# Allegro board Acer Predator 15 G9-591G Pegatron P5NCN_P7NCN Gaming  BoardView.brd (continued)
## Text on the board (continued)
IN2: list("[Spacing] IN2" "98.Line to Route Keepout" "0 MIL [DEFAULT]" "0 MIL" "0.00 MIL" "DRC ERROR CLASS/IN2" "[Shape] Route Keepout/In2 ((-630.0 2141.43) (-45.0 2716.89))" "[Line] N129963384 ((-343.9 2671.1) (-269.5 2745.5))" list(-318.110000 2696.890000) nil)@@@list("kelly1_pan" "2015/09/04 14:25:34" nil "P143000035-PC" "n3-p5-p7ncn.20")@@@list("jennifer_hsu" "2015/09/07 11:45:41" nil "P143000039-PC" "n3-p5-p7ncn.20") | list("[Spacing] IN2" "94.Shape to Route Keepin" "0 MIL [DEFAULT]" "0 MIL" "0.00 MIL" "DRC ERROR CLASS/IN2" "[Shape] Route Keepin/All ((-917.01 -373.7) (9771.34 6936.7))" "[In2 Shape] GND ((-137.47 -373.69) (9771.34 1245.0))" list(137.480000 381.890000) nil)@@@list("kelly1_pan" "2015/09/04 14:25:31" nil "P143000035-PC" "n3-p5-p7ncn.20")@@@list("jennifer_hsu" "2015/09/07 11:45:37" nil "P143000039-PC" "n3-p5-p7ncn.20") | list("[Spacing] IN2" "91.Shape to Route Keepin" "0 MIL [DEFAULT]" "0 MIL" "0.00 MIL" "DRC ERROR CLASS/IN2" "[Shape] Route Keepin/All ((-917.01 -373.7) (9771.34 6936.7))" "[In2 Shape] GND_LED ((5460.94 5736.53) (7231.96 6031.18))" list(6260.100000 5736.540000) nil)@@@list("kelly1_pan" "2015/09/04 14:25:28" nil "P143000035-PC" "n3-p5-p7ncn.20")@@@list("jennifer_hsu" "2015/09/07 11:45:35" nil "P143000039-PC" "n3-p5-p7ncn.20") | list("[Spacing] IN2" "92.Shape to Route Keepin" "0 MIL [DEFAULT]" "0 MIL" "0.00 MIL" "DRC ERROR CLASS/IN2" "[Shape] Route Keepin/All ((-917.01 -373.7) (9771.34 6936.7))" "[In2 Shape] LAN_GND ((9292.77 4680.51) (9698.51 5486.88))" list(9332.360000 5367.300000) nil)@@@list("kelly1_pan" "2015/09/04 14:25:29" nil "P143000035-PC" "n3-p5-p7ncn.20")@@@list("jennifer_hsu" "2015/09/07 11:45:36" nil "P143000039-PC" "n3-p5-p7ncn.20") | list("[Spacing] IN2" "93.Shape to Route Keepin" "0 MIL [DEFAULT]" "0 MIL" "0.00 MIL" "DRC ERROR CLASS/IN2" "[Shape] Route Keepin/All ((-917.01 -373.7) (9771.34 6936.7))" "[In2 Shape] GND ((9262.9 1450.04) (9668.98 2194.61))" list(9367.790000 1612.100000) nil)@@@list("kelly1_pan" "2015/09/04 14:25:30" nil "P143000035-PC" "n3-p5-p7ncn.20")@@@list("jennifer_hsu" "2015/09/07 11:45:37" nil "P143000039-PC" "n3-p5-p7ncn.20") | list("[Spacing] IN2" "96.Shape to Route Keepin" "0 MIL [DEFAULT]" "0 MIL" "0.00 MIL" "DRC ERROR CLASS/IN2" "[Shape] Route Keepin/All ((-917.01 -373.7) (9771.34 6936.7))" "[In2 Shape] GND ((-917.0 1310.0) (9698.51 6936.7))" list(9434.090000 2759.760000) nil)@@@list("kelly1_pan" "2015/09/04 14:25:33" nil "P143000035-PC" "n3-p5-p7ncn.20")@@@list("jennifer_hsu" "2015/09/07 11:45:39" nil "P143000039-PC" "n3-p5-p7ncn.20") | list("[Spacing] IN2" "97.Shape to Route Keepout" "0 MIL [DEFAULT]" "0 MIL" "0.00 MIL" "DRC ERROR CLASS/IN2" "[Shape] Route Keepout/All ((9638.0 5487.0) (9744.0 5507.0))" "[In2 Shape] GND ((-917.0 1310.0) (9698.51 6936.7))" list(9638.000000 5507.000000) nil)@@@list("kelly1_pan" "2015/09/04 14:25:33" nil "P143000035-PC" "n3-p5-p7ncn.20")@@@list("jennifer_hsu" "2015/09/07 11:45:39" nil "P143000039-PC" "n3-p5-p7ncn.20") | list("[Spacing] IN2" "95.Shape to Route Keepout" "0 MIL [DEFAULT]" "0 MIL" "0.00 MIL" "DRC ERROR CLASS/IN2" "[Shape] Route Keepout/All ((-937.01 -393.7) (9791.34 6956.69))" "[In2 Shape] GND ((-917.0 1310.0) (9698.51 6936.7))" list(9676.990000 2758.020000) nil)@@@list("kelly1_pan" "2015/09/04 14:25:32" nil "P143000035-PC" "n3-p5-p7ncn.20")@@@list("jennifer_hsu" "2015/09/07 11:45:38" nil "P143000039-PC" "n3-p5-p7ncn.20")
IN3: list("[Spacing] IN3" "104.Shape to Route Keepin" "0 MIL [DEFAULT]" "0 MIL" "0.00 MIL" "DRC ERROR CLASS/IN3" "[Shape] Route Keepin/All ((-917.01 -373.7) (9771.34 6936.7))" "[In3 Shape] GND ((-137.47 -373.69) (9771.34 1235.0))" list(137.480000 381.890000) nil)@@@list("kelly1_pan" "2015/09/04 14:25:39" nil "P143000035-PC" "n3-p5-p7ncn.20")@@@list("jennifer_hsu" "2015/09/07 11:45:45" nil "P143000039-PC" "n3-p5-p7ncn.20") | list("[Spacing] IN3" "99.Shape to Route Keepin" "0 MIL [DEFAULT]" "0 MIL" "0.00 MIL" "DRC ERROR CLASS/IN3" "[Shape] Route Keepin/All ((-917.01 -373.7) (9771.34 6936.7))" "[In3 Shape] GND_LED ((5460.94 5736.53) (7231.96 6031.18))" list(6260.100000 5736.540000) nil)@@@list("kelly1_pan" "2015/09/04 14:25:35" nil "P143000035-PC" "n3-p5-p7ncn.20")@@@list("jennifer_hsu" "2015/09/07 11:45:41" nil "P143000039-PC" "n3-p5-p7ncn.20") | list("[Spacing] IN3" "105.Shape to Route Keepin" "0 MIL [DEFAULT]" "0 MIL" "0.00 MIL" "DRC ERROR CLASS/IN3" "[Shape] Route Keepin/All ((-917.01 -373.7) (9771.34 6936.7))" "[In3 Shape] GND ((-917.0 1322.0) (9698.51 6936.7))" list(6742.230000 2896.930000) nil)@@@list("kelly1_pan" "2015/09/04 14:25:40" nil "P143000035-PC" "n3-p5-p7ncn.20")@@@list("jennifer_hsu" "2015/09/07 11:45:46" nil "P143000039-PC" "n3-p5-p7ncn.20") | list("[Spacing] IN3" "100.Shape to Route Keepin" "0 MIL [DEFAULT]" "0 MIL" "0.00 MIL" "DRC ERROR CLASS/IN3" "[Shape] Route Keepin/All ((-917.01 -373.7) (9771.34 6936.7))" "[In3 Shape] LAN_GND ((9292.77 4680.51) (9698.51 5486.88))" list(9332.360000 5367.300000) nil)@@@list("kelly1_pan" "2015/09/04 14:25:36" nil "P143000035-PC" "n3-p5-p7ncn.20")@@@list("jennifer_hsu" "2015/09/07 11:45:42" nil "P143000039-PC" "n3-p5-p7ncn.20") | list("[Spacing] IN3" "101.Shape to Route Keepin" "0 MIL [DEFAULT]" "0 MIL" "0.00 MIL" "DRC ERROR CLASS/IN3" "[Shape] Route Keepin/All ((-917.01 -373.7) (9771.34 6936.7))" "[In3 Shape] GND ((9256.0 1450.04) (9668.98 2194.61))" list(9367.790000 1612.100000) nil)@@@list("kelly1_pan" "2015/09/04 14:25:37" nil "P143000035-PC" "n3-p5-p7ncn.20")@@@list("jennifer_hsu" "2015/09/07 11:45:43" nil "P143000039-PC" "n3-p5-p7ncn.20") | list("[Spacing] IN3" "103.Shape to Route Keepin" "0 MIL [DEFAULT]" "0 MIL" "0.00 MIL" "DRC ERROR CLASS/IN3" "[Shape] Route Keepin/All ((-917.01 -373.7) (9771.34 6936.7))" "[In3 Shape] GND ((9258.0 2335.0) (9698.5 3131.19))" list(9368.890000 2739.600000) nil)@@@list("kelly1_pan" "2015/09/04 14:25:38" nil "P143000035-PC" "n3-p5-p7ncn.20")@@@list("jennifer_hsu" "2015/09/07 11:45:44" nil "P143000039-PC" "n3-p5-p7ncn.20") | list("[Spacing] IN3" "108.Shape to Route Keepout" "0 MIL [DEFAULT]" "0 MIL" "0.00 MIL" "DRC ERROR CLASS/IN3" "[Shape] Route Keepout/All ((9638.0 5487.0) (9744.0 5507.0))" "[In3 Shape] GND ((-917.0 1322.0) (9698.51 6936.7))" list(9638.000000 5507.000000) nil)@@@list("kelly1_pan" "2015/09/04 14:25:42" nil "P143000035-PC" "n3-p5-p7ncn.20")@@@list("jennifer_hsu" "2015/09/07 11:45:47" nil "P143000039-PC" "n3-p5-p7ncn.20") | list("[Spacing] IN3" "102.Shape to Route Keepout" "0 MIL [DEFAULT]" "0 MIL" "0.00 MIL" "DRC ERROR CLASS/IN3" "[Shape] Route Keepout/All ((-937.01 -393.7) (9791.34 6956.69))" "[In3 Shape] GND ((9258.0 2335.0) (9698.5 3131.19))" list(9676.990000 2758.020000) nil)@@@list("kelly1_pan" "2015/09/04 14:25:38" nil "P143000035-PC" "n3-p5-p7ncn.20")@@@list("jennifer_hsu" "2015/09/07 11:45:44" nil "P143000039-PC" "n3-p5-p7ncn.20") | list("[Spacing] IN3" "107.Shape to Route Keepout" "0 MIL [DEFAULT]" "0 MIL" "0.00 MIL" "DRC ERROR CLASS/IN3" "[Shape] Route Keepout/All ((9655.0 4660.5) (9762.0 4680.5))" "[In3 Shape] GND ((-917.0 1322.0) (9698.51 6936.7))" list(9678.600000 4660.500000) nil)@@@list("kelly1_pan" "2015/09/04 14:25:42" nil "P143000035-PC" "n3-p5-p7ncn.20")@@@list("jennifer_hsu" "2015/09/07 11:45:47" nil "P143000039-PC" "n3-p5-p7ncn.20") | list("[Spacing] IN3" "106.Shape to Route Keepout" "0 MIL [DEFAULT]" "0 MIL" "0.00 MIL" "DRC ERROR CLASS/IN3" "[Shape] Route Keepout/All ((8775.0 4660.0) (9725.0 5506.4))" "[In3 Shape] GND ((-917.0 1322.0) (9698.51 6936.7))" list(9678.600000 4660.000000) nil)@@@list("kelly1_pan" "2015/09/04 14:25:41" nil "P143000035-PC" "n3-p5-p7ncn.20")@@@list("jennifer_hsu" "2015/09/07 11:45:46" nil "P143000039-PC" "n3-p5-p7ncn.20")
GND3: list("[Spacing] GND3" "132.Shape to Route Keepout" "0 MIL [DEFAULT]" "0 MIL" "0.00 MIL" "DRC ERROR CLASS/GND3" "[Shape] Route Keepout/All ((-831.77 4457.88) (-768.15 4521.5))" "[Gnd3 Shape] +AC_BAT_SYS ((-885.0 1165.0) (230.0 6905.0))" list(-830.000000 4500.150000) nil)@@@list("kelly1_pan" "2015/09/04 14:26:00" nil "P143000035-PC" "n3-p5-p7ncn.20")@@@list("jennifer_hsu" "2015/09/07 11:46:08" nil "P143000039-PC" "n3-p5-p7ncn.20") | list("[Spacing] GND3" "128.Shape to Route Keepout" "0 MIL [DEFAULT]" "0 MIL" "0.00 MIL" "DRC ERROR CLASS/GND3" "[Shape] Route Keepout/All ((-831.77 5250.24) (-768.15 5313.86))" "[Gnd3 Shape] GND ((-917.01 -373.7) (9771.34 6936.7))" list(-829.340000 5294.250000) nil)@@@list("kelly1_pan" "2015/09/04 14:25:57" nil "P143000035-PC" "n3-p5-p7ncn.20")@@@list("jennifer_hsu" "2015/09/07 11:46:04" nil "P143000039-PC" "n3-p5-p7ncn.20") | list("[Spacing] GND3" "126.Shape to Route Keepout" "0 MIL [DEFAULT]" "0 MIL" "0.00 MIL" "DRC ERROR CLASS/GND3" "[Shape] Route Keepout/All ((-831.77 4457.88) (-768.15 4521.5))" "[Gnd3 Shape] GND ((-917.01 -373.7) (9771.34 6936.7))" list(-814.260000 4518.110000) nil)@@@list("kelly1_pan" "2015/09/04 14:25:56" nil "P143000035-PC" "n3-p5-p7ncn.20")@@@list("jennifer_hsu" "2015/09/07 11:46:02" nil "P143000039-PC" "n3-p5-p7ncn.20") | list("[Spacing] GND3" "140.Thru Pin to Shape" "5 MIL [DEFAULT]" "4.99 MIL" "0.01 MIL" "DRC ERROR CLASS/GND3" "[ThruPin] GND (<uTiL>cId65<uTiL>.50) (-256.51 2263.3)" "[Gnd3 Shape] AGND ((-610.0 2155.0) (-65.0 2696.89))" list(-265.000000 2254.810000) nil)@@@list("kelly1_pan" "2015/09/04 14:26:07" nil "P143000035-PC" "n3-p5-p7ncn.20")@@@list("jennifer_hsu" "2015/09/07 11:46:16" nil "P143000039-PC" "n3-p5-p7ncn.20") | list("[Spacing] GND3" "112.Thru Pin to Shape Same Net" "5 MIL [DEFAULT]" "0 MIL" "5.00 MIL" "DRC ERROR CLASS/GND3" "[ThruPin] GND (<uTiL>cId65<uTiL>.50) (-256.51 2263.3)" "[Gnd3 Shape] GND ((-917.01 -373.7) (9771.34 6936.7))" list(-255.000000 2275.200000) nil)@@@list("kelly1_pan" "2015/09/04 14:25:45" nil "P143000035-PC" "n3-p5-p7ncn.20")@@@list("jennifer_hsu" "2015/09/07 11:45:50" nil "P143000039-PC" "n3-p5-p7ncn.20") | list("[Spacing] GND3" "113.Thru Pin to Shape Same Net" "5 MIL [DEFAULT]" "0 MIL" "5.00 MIL" "DRC ERROR CLASS/GND3" "[ThruPin] GND (<uTiL>cId65<uTiL>.51) (-256.51 2422.28)" "[Gnd3 Shape] GND ((-917.01 -373.7) (9771.34 6936.7))" list(-249.320000 2431.890000) nil)@@@list("kelly1_pan" "2015/09/04 14:25:46" nil "P143000035-PC" "n3-p5-p7ncn.20")@@@list("jennifer_hsu" "2015/09/07 11:45:51" nil "P143000039-PC" "n3-p5-p7ncn.20") | list("[Spacing] GND3" "121.Shape to Route Keepout" "0 MIL [DEFAULT]" "0 MIL" "0.00 MIL" "DRC ERROR CLASS/GND3" "[Shape] Route Keepout/All ((-133.59 333.73) (-56.95 410.36))" "[Gnd3 Shape] GND ((-917.01 -373.7) (9771.34 6936.7))" list(-95.270000 410.360000) nil)@@@list("kelly1_pan" "2015/09/04 14:25:52" nil "P143000035-PC" "n3-p5-p7ncn.20")@@@list("jennifer_hsu" "2015/09/07 11:45:57" nil "P143000039-PC" "n3-p5-p7ncn.20") | list("[Spacing] GND3" "120.Shape to Route Keepout" "0 MIL [DEFAULT]" "0 MIL" "0.00 MIL" "DRC ERROR CLASS/GND3" "[Shape] Route Keepout/All ((-123.21 218.12) (-12.21 329.12))" "[Gnd3 Shape] GND ((-917.01 -373.7) (9771.34 6936.7))" list(-67.710000 329.120000) nil)@@@list("kelly1_pan" "2015/09/04 14:25:51" nil "P143000035-PC" "n3-p5-p7ncn.20")@@@list("jennifer_hsu" "2015/09/07 11:45:57" nil "P143000039-PC" "n3-p5-p7ncn.20") | list("[Spacing] GND3" "134.Shape to Thru Via" "5 MIL [DEFAULT]" "0 MIL" "5.00 MIL" "DRC ERROR CLASS/GND3" "[ThruVia] GND (VIA30D18A40) (249.0 5774.89)" "[Gnd3 Shape] +VCCGT ((-515.0 4910.0) (735.0 5765.0))" list(260.280000 5765.000000) nil)@@@list("kelly1_pan" "2015/09/04 14:26:02" nil "P143000035-PC" "n3-p5-p7ncn.20")@@@list("jennifer_hsu" "2015/09/07 11:46:11" nil "P143000039-PC" "n3-p5-p7ncn.20") | list("[Spacing] GND3" "117.Shape to Thru Via Same Net" "5 MIL [DEFAULT]" "0 MIL" "5.00 MIL" "DRC ERROR CLASS/GND3" "[ThruVia] GND (VIA30D18A40) (249.0 5774.89)" "[Gnd3 Shape] GND ((-917.01 -373.7) (9771.34 6936.7))" list(264.000000 5775.000000) nil)@@@list("kelly1_pan" "2015/09/04 14:25:49" nil "P143000035-PC" "n3-p5-p7ncn.20")@@@list("jennifer_hsu" "2015/09/07 11:45:54" nil "P143000039-PC" "n3-p5-p7ncn.20") | list("[Spacing] GND3" "136.Shape to Thru Via" "5 MIL [DEFAULT]" "0 MIL" "5.00 MIL" "DRC ERROR CLASS/GND3" "[ThruVia] GND (VIA30D18A40) (284.0 5774.89)" "[Gnd3 Shape] +VCCGT ((-515.0 4910.0) (735.0 5765.0))" list(295.280000 5765.000000) nil)@@@list("kelly1_pan" "2015/09/04 14:26:04" nil "P143000035-PC" "n3-p5-p7ncn.20")@@@list("jennifer_hsu" "2015/09/07 11:46:13" nil "P143000039-PC" "n3-p5-p7ncn.20") | list("[Spacing] GND3" "119.Shape to Thru Via Same Net" "5 MIL [DEFAULT]" "0 MIL" "5.00 MIL" "DRC ERROR CLASS/GND3" "[ThruVia] GND (VIA30D18A40) (284.0 5774.89)" "[Gnd3 Shape] GND ((-917.01 -373.7) (9771.34 6936.7))" list(299.000000 5775.000000) nil)@@@list("kelly1_pan" "2015/09/04 14:25:51" nil "P143000035-PC" "n3-p5-p7ncn.20")@@@list("jennifer_hsu" "2015/09/07 11:45:56" nil "P143000039-PC" "n3-p5-p7ncn.20") | list("[Spacing] GND3" "135.Shape to Thru Via" "5 MIL [DEFAULT]" "0 MIL" "5.00 MIL" "DRC ERROR CLASS/GND3" "[ThruVia] GND (VIA30D18A40) (319.0 5774.89)" "[Gnd3 Shape] +VCCGT ((-515.0 4910.0) (735.0 5765.0))" list(330.280000 5765.000000) nil)@@@list("kelly1_pan" "2015/09/04 14:26:03" nil "P143000035-PC" "n3-p5-p7ncn.20")@@@list("jennifer_hsu" "2015/09/07 11:46:12" nil "P143000039-PC" "n3-p5-p7ncn.20") | list("[Spacing] GND3" "118.Shape to Thru Via Same Net" "5 MIL [DEFAULT]" "0 MIL" "5.00 MIL" "DRC ERROR CLASS/GND3" "[ThruVia] GND (VIA30D18A40) (319.0 5774.89)" "[Gnd3 Shape] GND ((-917.01 -373.7) (9771.34 6936.7))" list(334.000000 5775.000000) nil)@@@list("kelly1_pan" "2015/09/04 14:25:50" nil "P143000035-PC" "n3-p5-p7ncn.20")@@@list("jennifer_hsu" "2015/09/07 11:45:55" nil "P143000039-PC" "n3-p5-p7ncn.20") | list("[Spacing] GND3" "133.Shape to Thru Via" "5 MIL [DEFAULT]" "0 MIL" "5.00 MIL" "DRC ERROR CLASS/GND3" "[ThruVia] GND (VIA18D8A28) (743.5 5438.5)" "[Gnd3 Shape] +VCCGT ((-515.0 4910.0) (735.0 5765.0))" list(735.000000 5441.460000) nil)@@@list("kelly1_pan" "2015/09/04 14:26:01" nil "P143000035-PC" "n3-p5-p7ncn.20")@@@list("jennifer_hsu" "2015/09/07 11:46:10" nil "P143000039-PC" "n3-p5-p7ncn.20") | list("[Spacing] GND3" "141.Shape to Thru Via" "5 MIL [DEFAULT]" "0 MIL" "5.00 MIL" "DRC ERROR CLASS/GND3" "[ThruVia] GND (VIA18D8A28) (743.5 5438.5)" "[Gnd3 Shape] +VCORE ((525.0 4910.0) (1445.0 6010.0))" list(745.000000 5447.370000) nil)@@@list("kelly1_pan" "2015/09/04 14:26:07" nil "P143000035-PC" "n3-p5-p7ncn.20")@@@list("jennifer_hsu" "2015/09/07 11:46:17" nil "P143000039-PC" "n3-p5-p7ncn.20") | list("[Spacing] GND3" "122.Shape to Route Keepout" "0 MIL [DEFAULT]" "0 MIL" "0.00 MIL" "DRC ERROR CLASS/GND3" "[Shape] Route Keepout/All ((1102.35 1665.34) (1165.35 1728.34))" "[Gnd3 Shape] GND ((-917.01 -373.7) (9771.34 6936.7))" list(1133.850000 1665.340000) nil)@@@list("kelly1_pan" "2015/09/04 14:25:53" nil "P143000035-PC" "n3-p5-p7ncn.20")@@@list("jennifer_hsu" "2015/09/07 11:45:59" nil "P143000039-PC" "n3-p5-p7ncn.20") | list("[Spacing] GND3" "123.Shape to Route Keepout" "0 MIL [DEFAULT]" "0 MIL" "0.00 MIL" "DRC ERROR CLASS/GND3" "[Shape] Route Keepout/All ((1508.04 1665.52) (1570.72 1728.2))" "[Gnd3 Shape] GND ((-917.01 -373.7) (9771.34 6936.7))" list(1539.380000 1665.520000) nil)@@@list("kelly1_pan" "2015/09/04 14:25:54" nil "P143000035-PC" "n3-p5-p7ncn.20")@@@list("jennifer_hsu" "2015/09/07 11:45:59" nil "P143000039-PC" "n3-p5-p7ncn.20") | list("[Spacing] GND3" "129.Shape to Route Keepout" "0 MIL [DEFAULT]" "0 MIL" "0.00 MIL" "DRC ERROR CLASS/GND3" "[Shape] Route Keepout/All ((1831.32 6634.59) (1885.01 6688.27))" "[Gnd3 Shape] GND ((-917.01 -373.7) (9771.34 6936.7))" list(1885.010000 6661.430000) nil)@@@list("kelly1_pan" "2015/09/04 14:25:58" nil "P143000035-PC" "n3-p5-p7ncn.20")@@@list("jennifer_hsu" "2015/09/07 11:46:05" nil "P143000039-PC" "n3-p5-p7ncn.20") | list("[Spacing] GND3" "115.Shape to Thru Via" "5 MIL [DEFAULT]" "0 MIL" "5.00 MIL" "DRC ERROR CLASS/GND3" "[ThruVia] GPIO2_GPU_EVENT# (VIA20D10A30) (2968.0 4040.0)" "[Gnd3 Shape] GND ((-917.01 -373.7) (9771.34 6936.7))" list(2959.340000 4045.000000) nil)@@@list("kelly1_pan" "2015/09/04 14:25:48" nil "P143000035-PC" "n3-p5-p7ncn.20")@@@list("jennifer_hsu" "2015/09/07 11:45:53" nil "P143000039-PC" "n3-p5-p7ncn.20") | list("[Spacing] GND3" "138.Shape to Thru Via" "5 MIL [DEFAULT]" "0 MIL" "5.00 MIL" "DRC ERROR CLASS/GND3" "[ThruVia] GPIO2_GPU_EVENT# (VIA20D10A30) (2968.0 4040.0)" "[Gnd3 Shape] +NVVDD ((2475.0 3190.0) (4740.0 5915.0))" list(2975.700000 4046.380000) nil)@@@list("kelly1_pan" "2015/09/04 14:26:05" nil "P143000035-PC" "n3-p5-p7ncn.20")@@@list("jennifer_hsu" "2015/09/07 11:46:14" nil "P143000039-PC" "n3-p5-p7ncn.20") | list("[Spacing] GND3" "130.Shape to Route Keepout" "0 MIL [DEFAULT]" "0 MIL" "0.00 MIL" "DRC ERROR CLASS/GND3" "[Shape] Route Keepout/All ((3022.0 6798.93) (3081.62 6858.55))" "[Gnd3 Shape] GND ((-917.01 -373.7) (9771.34 6936.7))" list(3051.810000 6858.550000) nil)@@@list("kelly1_pan" "2015/09/04 14:25:59" nil "P143000035-PC" "n3-p5-p7ncn.20")@@@list("jennifer_hsu" "2015/09/07 11:46:05" nil "P143000039-PC" "n3-p5-p7ncn.20") | list("[Spacing] GND3" "139.Shape to Thru Via Same Net" "5 MIL [DEFAULT]" "0 MIL" "5.00 MIL" "DRC ERROR CLASS/GND3" "[ThruVia] +NVVDD (VIA18D8A28) (3289.9 4776.8)" "[Gnd3 Shape] +NVVDD ((2475.0 3190.0) (4740.0 5915.0))" list(3293.120000 4785.200000) nil)@@@list("kelly1_pan" "2015/09/04 14:26:06" nil "P143000035-PC" "n3-p5-p7ncn.20")@@@list("jennifer_hsu" "2015/09/07 11:46:15" nil "P143000039-PC" "n3-p5-p7ncn.20") | list("[Spacing] GND3" "116.Shape to Thru Via" "5 MIL [DEFAULT]" "0 MIL" "5.00 MIL" "DRC ERROR CLASS/GND3" "[ThruVia] +NVVDD (VIA18D8A28) (3289.9 4776.8)" "[Gnd3 Shape] GND ((-917.01 -373.7) (9771.34 6936.7))" list(3298.900000 4776.830000) nil)@@@list("kelly1_pan" "2015/09/04 14:25:48" nil "P143000035-PC" "n3-p5-p7ncn.20")@@@list("jennifer_hsu" "2015/09/07 11:45:53" nil "P143000039-PC" "n3-p5-p7ncn.20") | list("[Spacing] GND3" "137.Shape to Thru Via" "5 MIL [DEFAULT]" "0 MIL" "5.00 MIL" "DRC ERROR CLASS/GND3" "[ThruVia] GND (VIA20D10A30) (3384.5 3629.6)" "[Gnd3 Shape] +NVVDD ((2475.0 3190.0) (4740.0 5915.0))" list(3390.960000 3621.960000) nil)@@@list("kelly1_pan" "2015/09/04 14:26:04" nil "P143000035-PC" "n3-p5-p7ncn.20")@@@list("jennifer_hsu" "2015/09/07 11:46:13" nil "P143000039-PC" "n3-p5-p7ncn.20") | list("[Spacing] GND3" "114.Shape to Thru Via Same Net" "5 MIL [DEFAULT]" "0 MIL" "5.00 MIL" "DRC ERROR CLASS/GND3" "[ThruVia] GND (VIA20D10A30) (3384.5 3629.6)" "[Gnd3 Shape] GND ((-917.01 -373.7) (9771.34 6936.7))" list(3393.800000 3633.270000) nil)@@@list("kelly1_pan" "2015/09/04 14:25:47" nil "P143000035-PC" "n3-p5-p7ncn.20")@@@list("jennifer_hsu" "2015/09/07 11:45:52" nil "P143000039-PC" "n3-p5-p7ncn.20") | list("[Spacing] GND3" "109.Shape to Route Keepout" "0 MIL [DEFAULT]" "0 MIL" "0.00 MIL" "DRC ERROR CLASS/GND3" "[Shape] Route Keepout/All ((6858.43 5535.43) (6984.05 5622.05))" "[Gnd3 Shape] GND_D-MIC R ((6566.9 5303.47) (7357.95 5617.8))" list(6883.030000 5617.800000) nil)@@@list("kelly1_pan" "2015/09/04 14:25:43" nil "P143000035-PC" "n3-p5-p7ncn.20")@@@list("jennifer_hsu" "2015/09/07 11:45:48" nil "P143000039-PC" "n3-p5-p7ncn.20") | list("[Spacing] GND3" "125.Shape to Route Keepout" "0 MIL [DEFAULT]" "0 MIL" "0.00 MIL" "DRC ERROR CLASS/GND3" "[Shape] Route Keepout/All ((8281.64 3112.35) (8348.26 3178.97))" "[Gnd3 Shape] GND ((-917.01 -373.7) (9771.34 6936.7))" list(8348.260000 3145.660000) nil)@@@list("kelly1_pan" "2015/09/04 14:25:55" nil "P143000035-PC" "n3-p5-p7ncn.20")@@@list("jennifer_hsu" "2015/09/07 11:46:01" nil "P143000039-PC" "n3-p5-p7ncn.20") | list("[Spacing] GND3" "124.Shape to Route Keepout" "0 MIL [DEFAULT]" "0 MIL" "0.00 MIL" "DRC ERROR CLASS/GND3" "[Shape] Route Keepout/All ((8396.75 1692.04) (8469.37 1764.66))" "[Gnd3 Shape] GND ((-917.01 -373.7) (9771.34 6936.7))" list(8469.370000 1728.350000) nil)@@@list("kelly1_pan" "2015/09/04 14:25:55" nil "P143000035-PC" "n3-p5-p7ncn.20")@@@list("jennifer_hsu" "2015/09/07 11:46:00" nil "P143000039-PC" "n3-p5-p7ncn.20") | list("[Spacing] GND3" "127.Shape to Route Keepout" "0 MIL [DEFAULT]" "0 MIL" "0.00 MIL" "DRC ERROR CLASS/GND3" "[Shape] Route Keepout/All ((8775.0 4660.0) (9725.0 5506.4))" "[Gnd3 Shape] GND ((-917.01 -373.7) (9771.34 6936.7))" list(9252.800000 4689.950000) nil)@@@list("kelly1_pan" "2015/09/04 14:25:57" nil "P143000035-PC" "n3-p5-p7ncn.20")@@@list("jennifer_hsu" "2015/09/07 11:46:03" nil "P143000039-PC" "n3-p5-p7ncn.20") | list("[Spacing] GND3" "110.Shape to Route Keepout" "0 MIL [DEFAULT]" "0 MIL" "0.00 MIL" "DRC ERROR CLASS/GND3" "[Shape] Route Keepout/All ((8775.0 4660.0) (9725.0 5506.4))" "[Gnd3 Shape] LAN_GND ((8795.0 4680.0) (9698.5 5487.0))" list(9289.360000 4680.000000) nil)@@@list("kelly1_pan" "2015/09/04 14:25:44" nil "P143000035-PC" "n3-p5-p7ncn.20")@@@list("jennifer_hsu" "2015/09/07 11:45:49" nil "P143000039-PC" "n3-p5-p7ncn.20") | list("[Spacing] GND3" "111.Shape to Route Keepin" "0 MIL [DEFAULT]" "0 MIL" "0.00 MIL" "DRC ERROR CLASS/GND3" "[Shape] Route Keepin/All ((-917.01 -373.7) (9771.34 6936.7))" "[Gnd3 Shape] LAN_GND ((8795.0 4680.0) (9698.5 5487.0))" list(9386.640000 5421.580000) nil)@@@list("kelly1_pan" "2015/09/04 14:25:44" nil "P143000035-PC" "n3-p5-p7ncn.20")@@@list("jennifer_hsu" "2015/09/07 11:45:49" nil "P143000039-PC" "n3-p5-p7ncn.20") | list("[Spacing] GND3" "131.Shape to Route Keepin" "0 MIL [DEFAULT]" "0 MIL" "0.00 MIL" "DRC ERROR CLASS/GND3" "[Shape] Route Keepin/All ((-917.01 -373.7) (9771.34 6936.7))" "[Gnd3 Shape] GND ((-917.01 -373.7) (9771.34 6936.7))" list(9433.500000 4571.180000) nil)@@@list("kelly1_pan" "2015/09/04 14:26:00" nil "P143000035-PC" "n3-p5-p7ncn.20")@@@list("jennifer_hsu" "2015/09/07 11:46:06" nil "P143000039-PC" "n3-p5-p7ncn.20")
IN4: list("[Spacing] IN4" "150.Line to Route Keepout" "0 MIL [DEFAULT]" "0 MIL" "0.00 MIL" "DRC ERROR CLASS/IN4" "[Shape] Route Keepout/In4 ((-630.0 2135.0) (-45.0 2716.89))" "[Line] AGND ((-165.0 2380.0) (-145.0 2506.89))" list(-155.000000 2451.890000) nil)@@@list("kelly1_pan" "2015/09/04 14:26:14" nil "P143000035-PC" "n3-p5-p7ncn.20")@@@list("jennifer_hsu" "2015/09/07 11:46:24" nil "P143000039-PC" "n3-p5-p7ncn.20") | list("[Spacing] IN4" "148.Shape to Route Keepin" "0 MIL [DEFAULT]" "0 MIL" "0.00 MIL" "DRC ERROR CLASS/IN4" "[Shape] Route Keepin/All ((-917.01 -373.7) (9771.34 6936.7))" "[In4 Shape] GND ((-917.0 -373.69) (9771.34 6936.7))" list(143.040000 430.660000) nil)@@@list("kelly1_pan" "2015/09/04 14:26:12" nil "P143000035-PC" "n3-p5-p7ncn.20")@@@list("jennifer_hsu" "2015/09/07 11:46:23" nil "P143000039-PC" "n3-p5-p7ncn.20") | list("[Spacing] IN4" "142.Shape to Route Keepin" "0 MIL [DEFAULT]" "0 MIL" "0.00 MIL" "DRC ERROR CLASS/IN4" "[Shape] Route Keepin/All ((-917.01 -373.7) (9771.34 6936.7))" "[In4 Shape] GND_LED ((5460.94 5736.53) (7231.96 6031.18))" list(6260.100000 5736.540000) nil)@@@list("kelly1_pan" "2015/09/04 14:26:08" nil "P143000035-PC" "n3-p5-p7ncn.20")@@@list("jennifer_hsu" "2015/09/07 11:46:18" nil "P143000039-PC" "n3-p5-p7ncn.20") | list("[Spacing] IN4" "144.Shape to Route Keepout" "0 MIL [DEFAULT]" "0 MIL" "0.00 MIL" "DRC ERROR CLASS/IN4" "[Shape] Route Keepout/In4 ((8741.14 1184.25) (8922.64 1365.75))" "[In4 Shape] VCC0P9_SVR ((8693.18 842.58) (8960.4 1371.3))" list(8787.100000 1184.250000) nil)@@@list("kelly1_pan" "2015/09/04 14:26:10" nil "P143000035-PC" "n3-p5-p7ncn.20")@@@list("jennifer_hsu" "2015/09/07 11:46:20" nil "P143000039-PC" "n3-p5-p7ncn.20") | list("[Spacing] IN4" "143.Shape to Route Keepin" "0 MIL [DEFAULT]" "0 MIL" "0.00 MIL" "DRC ERROR CLASS/IN4" "[Shape] Route Keepin/All ((-917.01 -373.7) (9771.34 6936.7))" "[In4 Shape] LAN_GND ((9292.77 4680.51) (9698.51 5486.88))" list(9332.360000 5367.300000) nil)@@@list("kelly1_pan" "2015/09/04 14:26:09" nil "P143000035-PC" "n3-p5-p7ncn.20")@@@list("jennifer_hsu" "2015/09/07 11:46:19" nil "P143000039-PC" "n3-p5-p7ncn.20") | list("[Spacing] IN4" "145.Shape to Route Keepin" "0 MIL [DEFAULT]" "0 MIL" "0.00 MIL" "DRC ERROR CLASS/IN4" "[Shape] Route Keepin/All ((-917.01 -373.7) (9771.34 6936.7))" "[In4 Shape] GND ((9218.0 3468.97) (9698.51 4719.09))" list(9426.850000 3554.310000) nil)@@@list("kelly1_pan" "2015/09/04 14:26:10" nil "P143000035-PC" "n3-p5-p7ncn.20")@@@list("jennifer_hsu" "2015/09/07 11:46:21" nil "P143000039-PC" "n3-p5-p7ncn.20") | list("[Spacing] IN4" "149.Shape to Route Keepout" "0 MIL [DEFAULT]" "0 MIL" "0.00 MIL" "DRC ERROR CLASS/IN4" "[Shape] Route Keepout/All ((9638.0 5487.0) (9744.0 5507.0))" "[In4 Shape] GND ((-917.0 -373.69) (9771.34 6936.7))" list(9638.000000 5507.000000) nil)@@@list("kelly1_pan" "2015/09/04 14:26:13" nil "P143000035-PC" "n3-p5-p7ncn.20")@@@list("jennifer_hsu" "2015/09/07 11:46:23" nil "P143000039-PC" "n3-p5-p7ncn.20") | list("[Spacing] IN4" "147.Shape to Route Keepout" "0 MIL [DEFAULT]" "0 MIL" "0.00 MIL" "DRC ERROR CLASS/IN4" "[Shape] Route Keepout/All ((9655.0 4660.5) (9762.0 4680.5))" "[In4 Shape] GND ((9218.0 3468.97) (9698.51 4719.09))" list(9678.600000 4660.500000) nil)@@@list("kelly1_pan" "2015/09/04 14:26:12" nil "P143000035-PC" "n3-p5-p7ncn.20")@@@list("jennifer_hsu" "2015/09/07 11:46:22" nil "P143000039-PC" "n3-p5-p7ncn.20") | list("[Spacing] IN4" "146.Shape to Route Keepout" "0 MIL [DEFAULT]" "0 MIL" "0.00 MIL" "DRC ERROR CLASS/IN4" "[Shape] Route Keepout/All ((8775.0 4660.0) (9725.0 5506.4))" "[In4 Shape] GND ((9218.0 3468.97) (9698.51 4719.09))" list(9678.600000 4660.000000) nil)@@@list("kelly1_pan" "2015/09/04 14:26:11" nil "P143000035-PC" "n3-p5-p7ncn.20")@@@list("jennifer_hsu" "2015/09/07 11:46:22" nil "P143000039-PC" "n3-p5-p7ncn.20")
GND4: list("[Spacing] GND4" "160.Thru Pin to Shape" "5 MIL [DEFAULT]" "4.99 MIL" "0.01 MIL" "DRC ERROR CLASS/GND4" "[ThruPin] GND (<uTiL>cId65<uTiL>.50) (-256.51 2263.3)" "[Gnd4 Shape] AGND ((-610.0 2155.0) (-65.0 2696.89))" list(-265.000000 2254.810000) nil)@@@list("kelly1_pan" "2015/09/04 14:26:24" nil "P143000035-PC" "n3-p5-p7ncn.20")@@@list("jennifer_hsu" "2015/09/07 11:46:32" nil "P143000039-PC" "n3-p5-p7ncn.20") | list("[Spacing] GND4" "153.Thru Pin to Shape Same Net" "5 MIL [DEFAULT]" "0 MIL" "5.00 MIL" "DRC ERROR CLASS/GND4" "[ThruPin] GND (<uTiL>cId65<uTiL>.50) (-256.51 2263.3)" "[Gnd4 Shape] GND ((-917.01 -373.7) (9771.34 6936.7))" list(-255.000000 2275.200000) nil)@@@list("kelly1_pan" "2015/09/04 14:26:16" nil "P143000035-PC" "n3-p5-p7ncn.20")@@@list("jennifer_hsu" "2015/09/07 11:46:27" nil "P143000039-PC" "n3-p5-p7ncn.20") | list("[Spacing] GND4" "154.Thru Pin to Shape Same Net" "5 MIL [DEFAULT]" "0 MIL" "5.00 MIL" "DRC ERROR CLASS/GND4" "[ThruPin] GND (<uTiL>cId65<uTiL>.51) (-256.51 2422.28)" "[Gnd4 Shape] GND ((-917.01 -373.7) (9771.34 6936.7))" list(-249.320000 2431.890000) nil)@@@list("kelly1_pan" "2015/09/04 14:26:17" nil "P143000035-PC" "n3-p5-p7ncn.20")@@@list("jennifer_hsu" "2015/09/07 11:46:28" nil "P143000039-PC" "n3-p5-p7ncn.20") | list("[Spacing] GND4" "157.Shape to Route Keepout" "0 MIL [DEFAULT]" "0 MIL" "0.00 MIL" "DRC ERROR CLASS/GND4" "[Shape] Route Keepout/All ((1831.32 6634.59) (1885.01 6688.27))" "[Gnd4 Shape] GND ((-917.01 -373.7) (9771.34 6936.7))" list(1885.010000 6661.430000) nil)@@@list("kelly1_pan" "2015/09/04 14:26:21" nil "P143000035-PC" "n3-p5-p7ncn.20")@@@list("jennifer_hsu" "2015/09/07 11:46:30" nil "P143000039-PC" "n3-p5-p7ncn.20") | list("[Spacing] GND4" "158.Shape to Route Keepout" "0 MIL [DEFAULT]" "0 MIL" "0.00 MIL" "DRC ERROR CLASS/GND4" "[Shape] Route Keepout/All ((3022.0 6798.93) (3081.62 6858.55))" "[Gnd4 Shape] GND ((-917.01 -373.7) (9771.34 6936.7))" list(3051.810000 6858.550000) nil)@@@list("kelly1_pan" "2015/09/04 14:26:22" nil "P143000035-PC" "n3-p5-p7ncn.20")@@@list("jennifer_hsu" "2015/09/07 11:46:30" nil "P143000039-PC" "n3-p5-p7ncn.20") | list("[Spacing] GND4" "155.Shape to Route Keepout" "0 MIL [DEFAULT]" "0 MIL" "0.00 MIL" "DRC ERROR CLASS/GND4" "[Shape] Route Keepout/All ((8396.75 1692.04) (8469.37 1764.66))" "[Gnd4 Shape] GND ((-917.01 -373.7) (9771.34 6936.7))" list(8469.370000 1728.350000) nil)@@@list("kelly1_pan" "2015/09/04 14:26:18" nil "P143000035-PC" "n3-p5-p7ncn.20")@@@list("jennifer_hsu" "2015/09/07 11:46:29" nil "P143000039-PC" "n3-p5-p7ncn.20") | list("[Spacing] GND4" "156.Shape to Route Keepout" "0 MIL [DEFAULT]" "0 MIL" "0.00 MIL" "DRC ERROR CLASS/GND4" "[Shape] Route Keepout/All ((8775.0 4660.0) (9725.0 5506.4))" "[Gnd4 Shape] GND ((-917.01 -373.7) (9771.34 6936.7))" list(9252.800000 4689.950000) nil)@@@list("kelly1_pan" "2015/09/04 14:26:19" nil "P143000035-PC" "n3-p5-p7ncn.20")@@@list("jennifer_hsu" "2015/09/07 11:46:29" nil "P143000039-PC" "n3-p5-p7ncn.20") | list("[Spacing] GND4" "151.Shape to Route Keepout" "0 MIL [DEFAULT]" "0 MIL" "0.00 MIL" "DRC ERROR CLASS/GND4" "[Shape] Route Keepout/All ((8775.0 4660.0) (9725.0 5506.4))" "[Gnd4 Shape] LAN_GND ((8795.0 4680.0) (9698.5 5487.0))" list(9289.360000 4680.000000) nil)@@@list("kelly1_pan" "2015/09/04 14:26:15" nil "P143000035-PC" "n3-p5-p7ncn.20")@@@list("jennifer_hsu" "2015/09/07 11:46:25" nil "P143000039-PC" "n3-p5-p7ncn.20") | list("[Spacing] GND4" "152.Shape to Route Keepin" "0 MIL [DEFAULT]" "0 MIL" "0.00 MIL" "DRC ERROR CLASS/GND4" "[Shape] Route Keepin/All ((-917.01 -373.7) (9771.34 6936.7))" "[Gnd4 Shape] LAN_GND ((8795.0 4680.0) (9698.5 5487.0))" list(9386.640000 5421.580000) nil)@@@list("kelly1_pan" "2015/09/04 14:26:16" nil "P143000035-PC" "n3-p5-p7ncn.20")@@@list("jennifer_hsu" "2015/09/07 11:46:26" nil "P143000039-PC" "n3-p5-p7ncn.20") | list("[Spacing] GND4" "159.Shape to Route Keepin" "0 MIL [DEFAULT]" "0 MIL" "0.00 MIL" "DRC ERROR CLASS/GND4" "[Shape] Route Keepin/All ((-917.01 -373.7) (9771.34 6936.7))" "[Gnd4 Shape] GND ((-917.01 -373.7) (9771.34 6936.7))" list(9433.500000 4571.180000) nil)@@@list("kelly1_pan" "2015/09/04 14:26:23" nil "P143000035-PC" "n3-p5-p7ncn.20")@@@list("jennifer_hsu" "2015/09/07 11:46:31" nil "P143000039-PC" "n3-p5-p7ncn.20")
User.28: 16 | 8 | 1 | 24 | 2 | CON1600 | H6901 | CON4301 | JP9601 | JP9600 | 260 | 259 | 5 | 9 | 13 | 15 | 10 | 6 | 11 | 36 | 12 | 30 | 20 | 19 | 50 | 64 | 32 | 96 | 4 | H64 | JP8059 | JP8060 | H51 | H12 | JP8053 | CON1700 | JP8050 | H61 | CON4500 | JP8055 | JP8054 | H11 | H63 | JP9500 | JP9501 | JP9502 | JP9300 | JP8303 | JP8304 | JP8301 | JP9000 | H69 | JP8901 | H56 | H68 | JP8902 | JP8904 | JP8400 | H67 | TOP | CON4402 | JP8109 | CON400 | H57 | JP8108 | JP8102 | H31 | JP8106 | JP9303 | JP8800 | JP8110 | JP8101 | JP8803 | H62 | JP8111 | JP8107 | H35 | H32 | JP8802 | JP8801 | JP8058 | JP8057 | JP8302 | JP8300 | CON3400 | CON4601 | CON5500 | CON5501 | CON4800 | CON1201 | JP8052 | JP8051 | REV:1.0 | P5-P7NCN_LED | PCB MADE IN | JP8100 | PEGATRON PROPRIETARY AND CONFIDENTIAL | TEL:(02)81439001 FAX:(02)28973868 | TAIPEI | www.pegatroncorp.com | DESIGNED BY PEGATRON CORPORATION | H55 | H66 | H53 | H65 | H54 | H52 | H60 | H704 | H302 | H701 | CON300 | H301 | CON402 | H703 | H702 | 2015/4/7 | 1.0/550 mils | CON301 | H802 | H800 | H803 | H801 | DESIGNER: | DATE: | LAY#: | 2015.03.27/18:53:12 | N3-P5-P7NCN.10 | KELLY1_PAN | P5NCN/P7NCN MAIN BOARD | P5NCN/P7NCN_PWR_BOARD | R&D DEPARTMENT/ENGINEER: | PROJECT DESCRIPTION: | MODEL NAME: | MAIN BOARD | BG1 NB4/Aliens Hsu | P5NCN/P7NCN | REV. | 1.0 | SILKSCREEN | PRIMARY-SIDE | 1ST
User.29: 20 | 10 | 30 | 60 | 40 | 50 | 37 | 25 | 5 | 15 | 35 | 55 | 45 | 1 | 13 | 2 | 9 | 7 | 259 | 260 | 6 | CON3700 | CON1601 | CON6003 | CON5000 | CON1701 | CON5602 | CON5100 | CON4400 | JP9401 | JP9400 | CON3100 | CON3110 | JP8201 | JP8903 | JP8202 | JP8900 | REV:1.0 | PCB MADE IN | P5-P7NCN_DMIC_L | CON5001 | BOT | CON3104 | JP8105 | CON3600 | P5NCN/P7NCN_DMIC_R | JP9302 | JP9301 | JP8804 | JP8805 | H6903 | CON6000 | CON6002 | H34 | CON5300 | CON2800 | H33 | 18 | 12 | CON6701 | CON6700 | CON6001 | CON5101 | P1 | S1 | CON5103 | JP9402 | JP8061 | CON5102 | JP8056 | JP8200 | JP8103 | JP8104 | PEGATRON PROPRIETARY AND CONFIDENTIAL | TEL:(02)81439001 FAX:(02)28973868 | TAIPEI | www.pegatroncorp.com | DESIGNED BY PEGATRON CORPORATION | H6902 | H401 | H402 | DESIGNER: | DATE: | LAY#: | 2015.03.27/18:53:12 | N3-P5-P7NCN.10 | KELLY1_PAN | R&D DEPARTMENT/ENGINEER: | PROJECT DESCRIPTION: | MODEL NAME: | MAIN BOARD | BG1 NB4/Aliens Hsu | P5NCN/P7NCN | REV. | 1.0 | SILKSCREEN | SECONDARY-SIDE | 2ND
